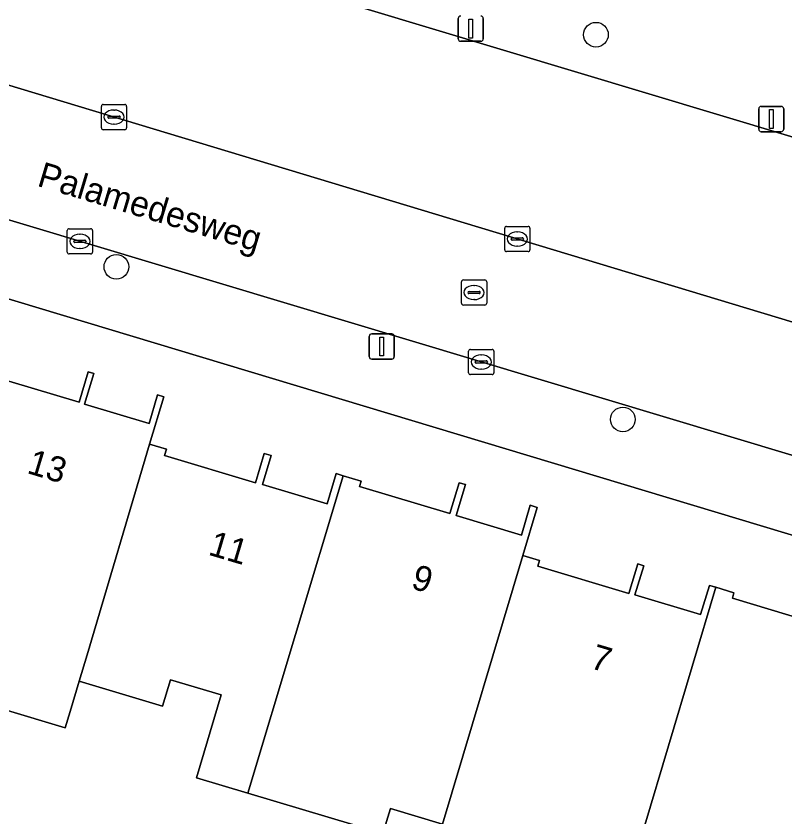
# Model space of a CAD drawing. Extents: x 162184 to 163154, y 385507 to 386516.
# Drawn here: x 162747.46 to 162777.97, y 386200.46 to 386232.21 of the extents above; entities that cross this region are included whole.
import ezdxf

# ---------------------------------------------------------------- set-up
doc = ezdxf.new("R2010")
doc.units = 0
for name, color, linetype in [('IMGEO_Boom', 7, 'Continuous'), ('IMGEO_Erf', 7, 'Continuous'), ('IMGEO_Groenvoorziening', 7, 'Continuous'), ('IMGEO_Kolk', 7, 'Continuous'), ('IMGEO_Lichtmast', 7, 'Continuous'), ('IMGEO_Openbare_ruimte_label', 7, 'Continuous'), ('IMGEO_Pand', 7, 'Continuous'), ('IMGEO_Pand_nummerreeks', 7, 'Continuous'), ('IMGEO_Parkeervlak_open', 7, 'Continuous'), ('IMGEO_Rijbaan_lokaal_open', 7, 'Continuous'), ('IMGEO_Rioolput', 7, 'Continuous'), ('IMGEO_Voetpad_open', 7, 'Continuous')]:
    doc.layers.add(name, color=color, linetype=linetype)

msp = doc.modelspace()

# ---------------------------------------------------------------- linework, layer by layer
at = {"layer": 'IMGEO_Boom'}
for centre in [(162770.469, 386231.475), (162751.446, 386222.271), (162771.537, 386216.22)]:
    msp.add_circle(centre, 0.489, dxfattribs=at)
at = {"layer": 'IMGEO_Erf'}
for points in [[(162799.034, 386202.871), (162799.086, 386203.08), (162799.119, 386203.292), (162799.133, 386203.507), (162799.127, 386203.722), (162799.102, 386203.936), (162799.059, 386204.146), (162798.997, 386204.352), (162798.916, 386204.552), (162798.818, 386204.743), (162798.704, 386204.925), (162798.573, 386205.096), (162798.428, 386205.255), (162798.269, 386205.4), (162798.098, 386205.531), (162797.916, 386205.645), (162797.725, 386205.743), (162797.525, 386205.823), (162797.422, 386205.857), (162732.623, 386225.378)], [(162746.277, 386218.005), (162749.965, 386216.9), (162750.328, 386218.109), (162750.547, 386218.043), (162750.181, 386216.824), (162752.74, 386216.057), (162753.08, 386217.192), (162753.329, 386217.117), (162752.766, 386215.24), (162753.435, 386215.04), (162753.36, 386214.79), (162756.959, 386213.712), (162757.307, 386214.872), (162757.582, 386214.79), (162757.238, 386213.644), (162759.802, 386212.875), (162760.16, 386214.071), (162760.445, 386213.986), (162761.157, 386213.772), (162761.094, 386213.563), (162764.676, 386212.489), (162765.042, 386213.71), (162765.296, 386213.634), (162764.927, 386212.405), (162767.51, 386211.631), (162767.865, 386212.815), (162768.141, 386212.732), (162767.568, 386210.821), (162768.229, 386210.623), (162768.161, 386210.397), (162771.777, 386209.313), (162772.129, 386210.488), (162772.362, 386210.418), (162772.016, 386209.262), (162774.621, 386208.48), (162774.969, 386209.641), (162775.226, 386209.564), (162775.945, 386209.348), (162775.88, 386209.13), (162779.526, 386208.037)], [(162764.382, 386200.173), (162762.316, 386200.792), (162762.018, 386199.799), (162756.666, 386201.404), (162754.625, 386202.016), (162755.608, 386205.294), (162753.593, 386205.898), (162753.279, 386204.849), (162749.968, 386205.842), (162749.608, 386204.641), (162749.413, 386203.989), (162742.011, 386206.207), (162741.907, 386205.86), (162739.847, 386206.477), (162734.536, 386208.068), (162734.836, 386209.069), (162732.73, 386209.7), (162733.698, 386212.928), (162728.382, 386214.522)]]:
    msp.add_lwpolyline(points, dxfattribs=at)
at = {"layer": 'IMGEO_Groenvoorziening'}
msp.add_lwpolyline([(162743.549, 386234.741), (162744.259, 386237.638), (162786.65, 386224.899), (162787.604, 386228.272), (162776.216, 386235.679), (162774.422, 386232.951), (162735.341, 386245.037), (162730.989, 386230.496)], dxfattribs=at)
at = {"layer": 'IMGEO_Kolk'}
for p, q in [((162750.927, 386228.707), (162751.779, 386228.707)), ((162750.852, 386227.781), (162750.852, 386228.633)), ((162751.34, 386228.487), (162751.365, 386228.487)), ((162751.853, 386228.633), (162751.853, 386227.781)), ((162751.111, 386228.201), (162751.111, 386228.213)), ((162751.549, 386228.164), (162751.151, 386228.164)), ((162751.154, 386228.25), (162751.552, 386228.25)), ((162751.595, 386228.213), (162751.595, 386228.201)), ((162751.363, 386227.927), (162751.338, 386227.927)), ((162751.779, 386227.707), (162750.927, 386227.707)), ((162749.498, 386222.854), (162749.498, 386223.706)), ((162749.573, 386223.78), (162750.425, 386223.78)), ((162750.499, 386223.706), (162750.499, 386222.854)), ((162766.849, 386222.949), (162766.849, 386223.801)), ((162766.924, 386223.875), (162767.776, 386223.875)), ((162767.337, 386223.655), (162767.362, 386223.655)), ((162767.85, 386223.801), (162767.85, 386222.949)), ((162749.8, 386223.323), (162750.198, 386223.323)), ((162749.986, 386223.56), (162750.011, 386223.56)), ((162767.108, 386223.369), (162767.108, 386223.381)), ((162767.546, 386223.332), (162767.148, 386223.332)), ((162767.151, 386223.418), (162767.549, 386223.418)), ((162767.592, 386223.381), (162767.592, 386223.369)), ((162749.757, 386223.274), (162749.757, 386223.286)), ((162750.195, 386223.237), (162749.797, 386223.237)), ((162750.009, 386223), (162749.984, 386223)), ((162750.241, 386223.286), (162750.241, 386223.274)), ((162767.36, 386223.095), (162767.335, 386223.095)), ((162750.425, 386222.78), (162749.573, 386222.78)), ((162767.776, 386222.875), (162766.924, 386222.875)), ((162765.419, 386218.072), (162765.419, 386218.924)), ((162765.494, 386218.998), (162766.346, 386218.998)), ((162766.42, 386218.924), (162766.42, 386218.072)), ((162765.721, 386218.541), (162766.119, 386218.541)), ((162765.907, 386218.778), (162765.932, 386218.778)), ((162765.678, 386218.492), (162765.678, 386218.504)), ((162766.116, 386218.455), (162765.718, 386218.455)), ((162766.162, 386218.504), (162766.162, 386218.492)), ((162766.346, 386217.998), (162765.494, 386217.998)), ((162765.93, 386218.218), (162765.905, 386218.218))]:
    msp.add_line(p, q, dxfattribs=at)
for points in [[(162750.927, 386228.707), (162751.779, 386228.707)], [(162750.852, 386227.781), (162750.852, 386228.633)], [(162751.853, 386228.633), (162751.853, 386227.781)], [(162751.779, 386227.707), (162750.927, 386227.707)], [(162749.498, 386222.854), (162749.498, 386223.706)], [(162749.573, 386223.78), (162750.425, 386223.78)], [(162750.499, 386223.706), (162750.499, 386222.854)], [(162766.849, 386222.949), (162766.849, 386223.801)], [(162766.924, 386223.875), (162767.776, 386223.875)], [(162767.85, 386223.801), (162767.85, 386222.949)], [(162750.425, 386222.78), (162749.573, 386222.78)], [(162767.776, 386222.875), (162766.924, 386222.875)], [(162765.419, 386218.072), (162765.419, 386218.924)], [(162765.494, 386218.998), (162766.346, 386218.998)], [(162766.42, 386218.924), (162766.42, 386218.072)], [(162766.346, 386217.998), (162765.494, 386217.998)]]:
    msp.add_lwpolyline(points, dxfattribs=at)
for centre, radius, start, end in [((162750.929, 386228.631), 0.0765, 91.552, 178.448), ((162750.929, 386228.631), 0.0765, 91.552, 178.448), ((162751.777, 386228.631), 0.0765, 1.552, 88.448), ((162751.777, 386228.631), 0.0765, 1.552, 88.448), ((162751.151, 386228.21), 0.0403, 85.8775, 175.7526), ((162751.148, 386228.2), 0.0366, 178.938, 274.7102), ((162751.552, 386228.207), 0.043, 264.8664, 352.4533), ((162751.556, 386228.212), 0.0386, 1.7309, 96.639), ((162750.929, 386227.783), 0.0765, 181.552, 268.448), ((162750.929, 386227.783), 0.0765, 181.552, 268.448), ((162751.777, 386227.783), 0.0765, 271.552, 358.448), ((162751.777, 386227.783), 0.0765, 271.552, 358.448), ((162749.575, 386223.704), 0.0765, 91.552, 178.448), ((162749.575, 386223.704), 0.0765, 91.552, 178.448), ((162750.423, 386223.704), 0.0765, 1.552, 88.448), ((162750.423, 386223.704), 0.0765, 1.552, 88.448), ((162766.926, 386223.799), 0.0765, 91.552, 178.448), ((162766.926, 386223.799), 0.0765, 91.552, 178.448), ((162767.774, 386223.799), 0.0765, 1.552, 88.448), ((162767.774, 386223.799), 0.0765, 1.552, 88.448), ((162749.797, 386223.283), 0.0403, 85.8775, 175.7526), ((162750.202, 386223.285), 0.0386, 1.7309, 96.639), ((162767.148, 386223.378), 0.0403, 85.8775, 175.7526), ((162767.145, 386223.368), 0.0366, 178.938, 274.7102), ((162767.549, 386223.375), 0.043, 264.8664, 352.4533), ((162767.553, 386223.38), 0.0386, 1.7309, 96.639), ((162749.794, 386223.273), 0.0366, 178.938, 274.7102), ((162750.198, 386223.28), 0.043, 264.8664, 352.4533), ((162749.575, 386222.856), 0.0765, 181.552, 268.448), ((162749.575, 386222.856), 0.0765, 181.552, 268.448), ((162750.423, 386222.856), 0.0765, 271.552, 358.448), ((162750.423, 386222.856), 0.0765, 271.552, 358.448), ((162766.926, 386222.951), 0.0765, 181.552, 268.448), ((162766.926, 386222.951), 0.0765, 181.552, 268.448), ((162767.774, 386222.951), 0.0765, 271.552, 358.448), ((162767.774, 386222.951), 0.0765, 271.552, 358.448), ((162765.496, 386218.922), 0.0765, 91.552, 178.448), ((162765.496, 386218.922), 0.0765, 91.552, 178.448), ((162766.344, 386218.922), 0.0765, 1.552, 88.448), ((162766.344, 386218.922), 0.0765, 1.552, 88.448), ((162765.718, 386218.501), 0.0403, 85.8775, 175.7526), ((162766.123, 386218.503), 0.0386, 1.7309, 96.639), ((162765.715, 386218.491), 0.0366, 178.938, 274.7102), ((162766.119, 386218.498), 0.043, 264.8664, 352.4533), ((162765.496, 386218.074), 0.0765, 181.552, 268.448), ((162765.496, 386218.074), 0.0765, 181.552, 268.448), ((162766.344, 386218.074), 0.0765, 271.552, 358.448), ((162766.344, 386218.074), 0.0765, 271.552, 358.448)]:
    msp.add_arc(centre, radius, start, end, dxfattribs=at)
for centre, major_axis, ratio, start_param, end_param in [((162751.339, 386228.207), (-0.387, 0.002), 0.722429, 4.712389, 7.853982), ((162751.364, 386228.207), (-0.39, 0.002), 0.717154, 1.570796, 4.712389), ((162767.336, 386223.375), (-0.387, 0.002), 0.722429, 4.712389, 7.853982), ((162767.361, 386223.375), (-0.39, 0.002), 0.717154, 1.570796, 4.712389), ((162749.985, 386223.28), (-0.387, 0.002), 0.722429, 4.712389, 7.853982), ((162750.01, 386223.28), (-0.39, 0.002), 0.717154, 1.570796, 4.712389), ((162765.906, 386218.498), (-0.387, 0.002), 0.722429, 4.712389, 7.853982), ((162765.931, 386218.498), (-0.39, 0.002), 0.717154, 1.570796, 4.712389)]:
    msp.add_ellipse(centre, major_axis=major_axis, ratio=ratio, start_param=start_param, end_param=end_param, dxfattribs=at)
at = {"layer": 'IMGEO_Lichtmast'}
for p, q in [((162765.007, 386231.315), (162765.007, 386232.115)), ((162765.007, 386232.115), (162765.007, 386231.315)), ((162765.997, 386232.115), (162765.997, 386231.315)), ((162765.997, 386231.315), (162765.997, 386232.115)), ((162765.897, 386231.215), (162765.107, 386231.215)), ((162765.107, 386231.215), (162765.897, 386231.215)), ((162776.927, 386227.729), (162776.927, 386228.529)), ((162776.927, 386228.529), (162776.927, 386227.729)), ((162777.027, 386228.629), (162777.817, 386228.629)), ((162777.817, 386228.629), (162777.027, 386228.629)), ((162777.917, 386228.529), (162777.917, 386227.729)), ((162777.917, 386227.729), (162777.917, 386228.529)), ((162777.817, 386227.629), (162777.027, 386227.629)), ((162777.027, 386227.629), (162777.817, 386227.629)), ((162761.477, 386218.711), (162761.477, 386219.511)), ((162761.477, 386219.511), (162761.477, 386218.711)), ((162761.577, 386219.611), (162762.367, 386219.611)), ((162762.367, 386219.611), (162761.577, 386219.611)), ((162762.467, 386219.511), (162762.467, 386218.711)), ((162762.467, 386218.711), (162762.467, 386219.511)), ((162762.367, 386218.611), (162761.577, 386218.611)), ((162761.577, 386218.611), (162762.367, 386218.611))]:
    msp.add_line(p, q, dxfattribs=at)
for points in [[(162765.427, 386232.09), (162765.577, 386232.09), (162765.577, 386231.34), (162765.427, 386231.34), (162765.427, 386232.09)], [(162777.347, 386228.504), (162777.497, 386228.504), (162777.497, 386227.754), (162777.347, 386227.754), (162777.347, 386228.504)], [(162761.897, 386219.486), (162762.047, 386219.486), (162762.047, 386218.736), (162761.897, 386218.736), (162761.897, 386219.486)]]:
    msp.add_lwpolyline(points, dxfattribs=at)
for centre, start, end in [((162765.107, 386232.115), 90, 180), ((162765.107, 386232.115), 90, 180), ((162765.897, 386232.115), 0, 90), ((162765.897, 386232.115), 360, 90), ((162765.107, 386231.315), 180, 270), ((162765.107, 386231.315), 180, 270), ((162765.897, 386231.315), 270, 0), ((162765.897, 386231.315), 270, 0), ((162777.027, 386228.529), 90, 180), ((162777.027, 386228.529), 90, 180), ((162777.817, 386228.529), 0, 90), ((162777.817, 386228.529), 360, 90), ((162777.027, 386227.729), 180, 270), ((162777.027, 386227.729), 180, 270), ((162777.817, 386227.729), 270, 0), ((162777.817, 386227.729), 270, 0), ((162761.577, 386219.511), 90, 180), ((162761.577, 386219.511), 90, 180), ((162762.367, 386219.511), 0, 90), ((162762.367, 386219.511), 360, 90), ((162761.577, 386218.711), 180, 270), ((162761.577, 386218.711), 180, 270), ((162762.367, 386218.711), 270, 0), ((162762.367, 386218.711), 270, 0)]:
    msp.add_arc(centre, 0.1, start, end, dxfattribs=at)
at = {"layer": 'IMGEO_Pand'}
for points in [[(162752.766, 386215.24), (162753.329, 386217.117), (162753.08, 386217.192), (162752.74, 386216.057), (162750.181, 386216.824), (162750.547, 386218.043), (162750.328, 386218.109), (162749.965, 386216.9), (162746.277, 386218.005), (162746.343, 386218.225), (162745.669, 386218.427), (162742.206, 386206.859), (162742.011, 386206.207), (162749.413, 386203.989), (162749.608, 386204.641), (162749.968, 386205.842), (162750.282, 386206.89)], [(162760.445, 386213.986), (162760.16, 386214.071), (162759.802, 386212.875), (162757.238, 386213.644), (162757.582, 386214.79), (162757.307, 386214.872), (162756.959, 386213.712), (162753.36, 386214.79), (162753.435, 386215.04), (162752.766, 386215.24), (162750.282, 386206.89), (162749.968, 386205.842), (162753.279, 386204.849), (162753.593, 386205.898), (162755.608, 386205.294), (162754.625, 386202.016), (162756.666, 386201.404)], [(162764.382, 386200.173), (162767.568, 386210.821), (162768.141, 386212.732), (162767.865, 386212.815), (162767.51, 386211.631), (162764.927, 386212.405), (162765.296, 386213.634), (162765.042, 386213.71), (162764.676, 386212.489), (162761.094, 386213.563), (162761.157, 386213.772), (162760.445, 386213.986), (162756.666, 386201.404), (162762.018, 386199.799), (162762.316, 386200.792)], [(162772.407, 386200.134), (162775.226, 386209.564), (162774.969, 386209.641), (162774.621, 386208.48), (162772.016, 386209.262), (162772.362, 386210.418), (162772.129, 386210.488), (162771.777, 386209.313), (162768.161, 386210.397), (162768.229, 386210.623), (162767.568, 386210.821), (162764.382, 386200.173), (162764.099, 386199.224), (162769.434, 386197.595), (162771.463, 386196.986)], [(162782.395, 386206.4), (162782.985, 386208.371), (162782.731, 386208.447), (162782.356, 386207.199), (162779.759, 386207.978), (162780.115, 386209.164), (162779.884, 386209.233), (162779.526, 386208.037), (162775.88, 386209.13), (162775.945, 386209.348), (162775.226, 386209.564), (162772.407, 386200.134), (162775.602, 386199.175), (162774.947, 386196.991), (162776.736, 386196.454), (162776.095, 386194.316), (162778.556, 386193.578), (162779.204, 386195.737)]]:
    msp.add_lwpolyline(points, close=True, dxfattribs=at)
at = {"layer": 'IMGEO_Parkeervlak_open'}
for points in [[(162785.293, 386220.102), (162786.65, 386224.899), (162744.259, 386237.638), (162743.549, 386234.741)], [(162741.125, 386231.297), (162786.507, 386217.588)]]:
    msp.add_lwpolyline(points, dxfattribs=at)
at = {"layer": 'IMGEO_Rijbaan_lokaal_open'}
for points in [[(162801.281, 386213.222), (162800.328, 386213.502), (162786.507, 386217.588), (162741.125, 386231.297)], [(162736.303, 386230.68), (162735.374, 386227.671), (162798.523, 386208.705), (162798.77, 386208.624), (162799.211, 386208.445), (162799.633, 386208.228), (162800.035, 386207.974), (162800.412, 386207.685), (162800.762, 386207.364), (162801.082, 386207.012), (162801.369, 386206.633), (162801.621, 386206.231), (162801.836, 386205.807), (162802.013, 386205.366), (162802.149, 386204.91), (162802.244, 386204.445), (162802.298, 386203.973), (162802.308, 386203.498), (162802.277, 386203.023), (162802.203, 386202.554), (162805.951, 386214.949)]]:
    msp.add_lwpolyline(points, dxfattribs=at)
at = {"layer": 'IMGEO_Rioolput'}
for p, q in [((162765.209, 386221.752), (162766.061, 386221.752)), ((162765.134, 386220.826), (162765.134, 386221.678)), ((162765.622, 386221.532), (162765.647, 386221.532)), ((162766.135, 386221.678), (162766.135, 386220.826)), ((162765.393, 386221.246), (162765.393, 386221.258)), ((162765.831, 386221.209), (162765.433, 386221.209)), ((162765.436, 386221.295), (162765.834, 386221.295)), ((162765.877, 386221.258), (162765.877, 386221.246)), ((162765.645, 386220.972), (162765.62, 386220.972)), ((162766.061, 386220.752), (162765.209, 386220.752))]:
    msp.add_line(p, q, dxfattribs=at)
for points in [[(162765.209, 386221.752), (162766.061, 386221.752)], [(162765.134, 386220.826), (162765.134, 386221.678)], [(162766.135, 386221.678), (162766.135, 386220.826)], [(162766.061, 386220.752), (162765.209, 386220.752)]]:
    msp.add_lwpolyline(points, dxfattribs=at)
for centre, radius, start, end in [((162765.211, 386221.676), 0.0765, 91.552, 178.448), ((162765.211, 386221.676), 0.0765, 91.552, 178.448), ((162766.059, 386221.676), 0.0765, 1.552, 88.448), ((162766.059, 386221.676), 0.0765, 1.552, 88.448), ((162765.433, 386221.255), 0.0403, 85.8775, 175.7526), ((162765.43, 386221.245), 0.0366, 178.938, 274.7102), ((162765.834, 386221.252), 0.043, 264.8664, 352.4533), ((162765.838, 386221.257), 0.0386, 1.7309, 96.639), ((162765.211, 386220.828), 0.0765, 181.552, 268.448), ((162765.211, 386220.828), 0.0765, 181.552, 268.448), ((162766.059, 386220.828), 0.0765, 271.552, 358.448), ((162766.059, 386220.828), 0.0765, 271.552, 358.448)]:
    msp.add_arc(centre, radius, start, end, dxfattribs=at)
for centre, major_axis, ratio, start_param, end_param in [((162765.621, 386221.252), (-0.387, 0.002), 0.722429, 4.712389, 7.853982), ((162765.646, 386221.252), (-0.39, 0.002), 0.717154, 1.570796, 4.712389)]:
    msp.add_ellipse(centre, major_axis=major_axis, ratio=ratio, start_param=start_param, end_param=end_param, dxfattribs=at)
at = {"layer": 'IMGEO_Voetpad_open'}
for points in [[(162798.523, 386208.705), (162735.374, 386227.671)], [(162732.623, 386225.378), (162797.422, 386205.857)]]:
    msp.add_lwpolyline(points, dxfattribs=at)

# ---------------------------------------------------------------- texts
at = {"layer": 'IMGEO_Openbare_ruimte_label'}
msp.add_text('Palamedesweg', height=1, rotation=343.2678, dxfattribs=at).set_placement((162748.262, 386225.49))
at = {"layer": 'IMGEO_Pand_nummerreeks'}
for s, rotation, p in [('13', 343.2295, (162747.859, 386214.103)), ('11', 343.4472, (162755.052, 386210.865)), ('9', 343.2418, (162763.093, 386209.535)), ('7', 343.4718, (162770.194, 386206.372))]:
    msp.add_text(s, height=1, rotation=rotation, dxfattribs=at).set_placement(p)

doc.saveas('drawing.dxf')
